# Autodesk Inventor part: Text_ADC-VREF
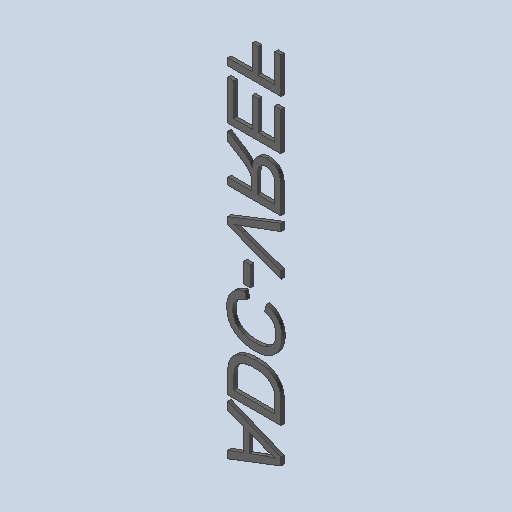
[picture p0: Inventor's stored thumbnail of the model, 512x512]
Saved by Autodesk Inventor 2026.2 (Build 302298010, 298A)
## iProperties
Created: 2026-10
Part Number: Text_ADC-VREF
Material: Générique
Document SubType Name: Modeling
Designer: mel
Density: 1 g/cm^3
Appearance: Par défaut
Author: mel
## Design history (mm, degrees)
feature "Base1"
feature "Base2"
feature "Base3"
feature "Base4"
feature "Base5"
feature "Base6"
feature "Base7"
feature "Base8"
node "Solide1"
node "Solide2"
node "Solide3"
node "Solide4"
node "Solide5"
node "Solide6"
node "Solide7"
node "Solide8"
